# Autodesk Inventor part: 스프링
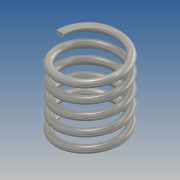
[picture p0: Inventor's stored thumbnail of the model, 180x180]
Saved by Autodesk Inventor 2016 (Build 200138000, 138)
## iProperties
Created: 2016-03
Part Number: 스프링
Material: 스테인레스 스틸
Document SubType Name: Modeling
Designer: Administrator
Density: 8 g/cm^3
Appearance: 반연마
Mass: 6.57426 g
Surface Area: 16.7376 cm^2
Volume: 0.821783 cm^3
Author: Administrator
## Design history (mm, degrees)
sketch "스케치1"
  geometry: L1 (0, 0)-(8.5, 0); L2 (8.5, 0)-(8.5, 20.5); L3 (8.5, 20.5)-(0, 20.5); L4 (0, 20.5)-(0, 0); C1 r 1 at (8.5, 0)
  constraints: 8 end point, 2 parallel, 1 centre point, 1 coincident, 1 horizontal, 1 perpendicular
  dimensions: "d0" = 20.5 distance of L1.end L2.end (derived); "d1" = 17 diameter of L2 L4; "d2" = 2 diameter of C1
feature "코일1" pitch "d3" = 10; turns "d5" = 5; dims "d4" = 20.5 (= d0), "d6" = 0, angle "d7" = 90 deg, angle "d8" = 90 deg, "d9" = 0, "d10" = 0
sketch "스케치2"
  geometry: L1 (4.1, 0)-(-21.424, 0); L2 (-21.424, 0)-(-21.424, -13.495); L3 (-21.424, -13.495)-(4.1, -13.495); L4 (4.1, -13.495)-(4.1, 0); 3 further points
  constraints: 8 end point, 2 parallel, 1 horizontal, 1 horizontal alignment, 1 perpendicular, 1 point on line
extrude "돌출1" cut sketch "스케치2" stored distance "d11" = 0; taper "d12" = 0 deg
sketch "스케치3"
  geometry: L1 (-2.819, 0)-(17.433, 0); L2 (17.433, 0)-(17.433, 5.421); L3 (17.433, 5.421)-(-2.819, 5.421); L4 (-2.819, 5.421)-(-2.819, 0); 3 further points
  constraints: 8 end point, 2 parallel, 1 horizontal, 1 horizontal alignment, 1 perpendicular, 1 point on line
extrude "돌출2" cut sketch "스케치3" stored distance "d13" = 0; taper "d14" = 0 deg
node "솔리드1"
